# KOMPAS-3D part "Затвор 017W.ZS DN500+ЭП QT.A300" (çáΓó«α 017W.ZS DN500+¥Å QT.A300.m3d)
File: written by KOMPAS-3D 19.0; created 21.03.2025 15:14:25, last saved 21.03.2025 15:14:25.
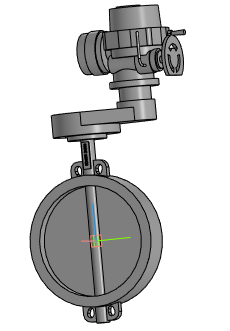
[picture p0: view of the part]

Document properties: Полное имя файла: Затвор 017W.ZS DN500+ЭП QT.A300.a3d

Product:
- Part/product: Затвор 017W.ZS DN500+ЭП QT.A300
    Масса: 363.173

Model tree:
1. Операция без истории:1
